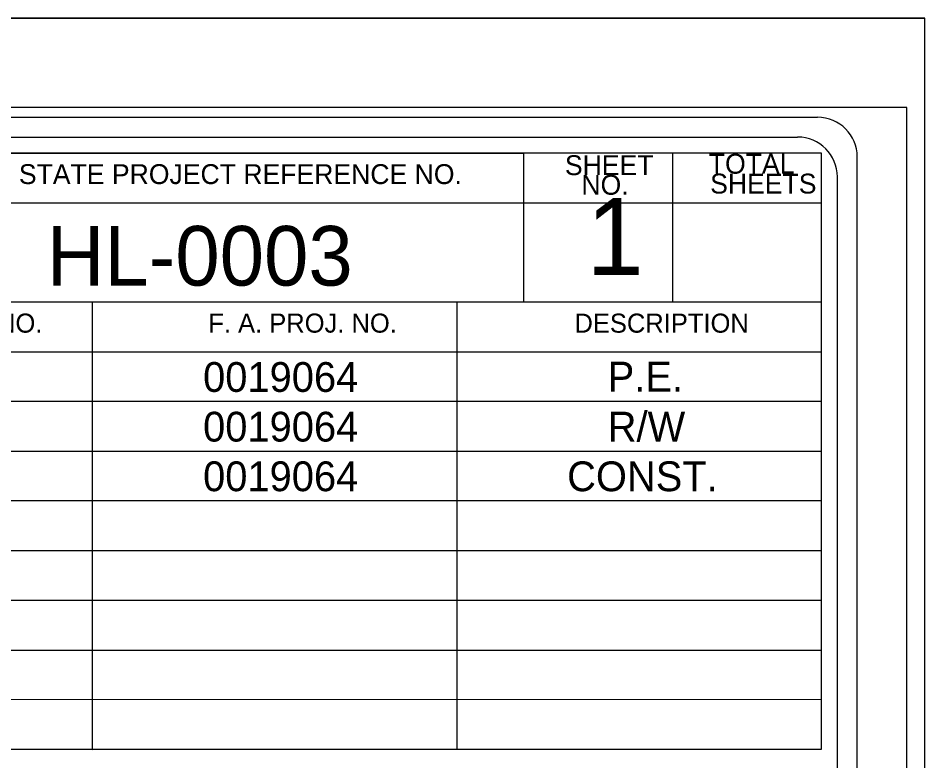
# Model space of a CAD drawing. Extents: x 925297 to 940193, y 663541 to 689899.
# Drawn here: x 936944 to 938769, y 688403 to 689899 of the extents above; entities that cross this region are included whole.
import ezdxf

# ---------------------------------------------------------------- set-up
doc = ezdxf.new("R2010")
doc.units = 0
for name, color, linetype in [('Sheet Cutting Line CELL', 7, 'Continuous'), ('Sheet Data Field CELL', 7, 'Continuous'), ('Sheet Plot Border Inside CELL', 7, 'Continuous'), ('Sheet Plot Border Outside CELL', 7, 'Continuous'), ('Sheet Title CELL', 7, 'Continuous')]:
    doc.layers.add(name, color=color, linetype=linetype)

msp = doc.modelspace()

# ---------------------------------------------------------------- linework, layer by layer
at = {"layer": 'Sheet Cutting Line CELL'}
msp.add_line((925296.7, 689898.6), (938768.7, 689898.6), dxfattribs=at)
at = {"layer": 'Sheet Plot Border Inside CELL'}
msp.add_lwpolyline([(925400.7, 681278.2), (938732.7, 681278.2), (938732.7, 689719), (925400.7, 689719)], close=True, dxfattribs=at)
at = {"layer": 'Sheet Plot Border Outside CELL'}
msp.add_lwpolyline([(938768.7, 689898.6), (925296.7, 689898.6), (925296.7, 681098.7), (938768.7, 681098.7)], close=True, dxfattribs=at)
at = {"layer": 'Sheet Title CELL'}
for points in [[(938552.8, 689698.6), (926712.6, 689698.7)], [(938512.7, 689658.6), (927152.8, 689658.6)], [(936360.7, 689526.7), (938560.7, 689526.7), (938560.7, 689626.7), (936360.7, 689626.6)], [(936660.7, 689626.7), (937960.8, 689626.6), (937960.7, 689326.7), (937827.1, 689326.7), (937827.1, 688426.7), (938560.7, 688426.7), (938560.7, 689626.7), (938260.7, 689626.7), (938260.8, 689326.7)], [(938632.7, 681378.7), (938632.7, 689618.6)], [(938592.7, 682898.6), (938592.7, 689578.7)], [(936360.7, 689226.6), (938560.7, 689226.6), (938560.7, 689326.7), (936360.7, 689326.7)], [(936360.7, 688426.7), (937093.9, 688426.6), (937093.9, 689326.6), (936660.7, 689326.6)], [(936360.7, 689026.6), (938560.7, 689026.7), (938560.7, 689126.6), (936360.7, 689126.6)], [(936360.7, 688826.7), (938560.7, 688826.7), (938560.7, 688926.7), (936360.7, 688926.7)], [(936360.7, 688626.6), (938560.7, 688626.6), (938560.7, 688726.6), (936360.8, 688726.6)], [(936360.7, 688426.7), (938560.7, 688426.7), (938560.7, 688526.6), (936360.7, 688526.7)]]:
    msp.add_lwpolyline(points, dxfattribs=at)
for centre in [(938552.7, 689619.1), (938512.7, 689579.1)]:
    msp.add_arc(centre, 80, 0, 90, dxfattribs=at)

# ---------------------------------------------------------------- texts
at = {"layer": 'Sheet Data Field CELL'}
for s, height, p in [('HL-0003', 120, (937001.8, 689360.2)), ('0019064', 60, (937316.2, 689146.2)), ('P.E.', 60, (938130.4, 689147)), ('0019064', 60, (937316.2, 689046.2)), ('R/W', 60, (938130.5, 689046.3)), ('0019064', 60, (937316.2, 688946.3)), ('CONST.', 60, (938048.8, 688946.3))]:
    msp.add_text(s, height=height, dxfattribs=at).set_placement(p)
at = {"layer": 'Sheet Title CELL'}
for s, height, p in [('SHEET', 40, (938044.3, 689582.6)), ('TOTAL', 40, (938333.9, 689585.5)), ('STATE PROJECT REFERENCE NO.', 39.998, (936945.5, 689564.6)), ('NO.', 40, (938077.5, 689543.1)), ('SHEETS', 40, (938336.6, 689545.5)), ('1', 154.8, (938087.5, 689381.5)), ('STATE PROJ. NO.', 38.4, (936556.3, 689265.5)), ('F. A. PROJ. NO.', 38.4, (937326.7, 689265.5)), ('DESCRIPTION', 38.4, (938063.5, 689265.4))]:
    msp.add_text(s, height=height, rotation=360, dxfattribs=at).set_placement(p)

doc.saveas('drawing.dxf')
